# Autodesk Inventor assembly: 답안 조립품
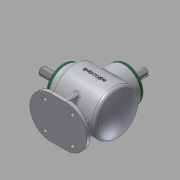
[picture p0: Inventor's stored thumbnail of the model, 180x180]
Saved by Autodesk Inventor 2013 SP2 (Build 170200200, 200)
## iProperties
Created: 2023-01
Part Number: 답안 조립품
Document SubType Name: Assembly
Designer: aa
Author: aa
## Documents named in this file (14)
- C:\Users\aa\Desktop\730106V1028\730106V1028\답안 조립품.iam
- C:\Users\aa\Desktop\730106V1025\본체.ipt
- C:\Users\aa\Desktop\730106V1025\서브 베벨기어.ipt
- C:\Users\aa\Desktop\730106V1025\오일실 17 32 8.ipt
- C:\Users\aa\Desktop\730106V1025\커버.ipt
- C:\Users\aa\Desktop\730106V1025\메인 베벨기어.ipt
- C:\Users\aa\Desktop\730106V1025\베어링 6203.ipt
- C:\Users\aa\Desktop\730106V1025\M4.ipt
- C:\Users\aa\Desktop\730106V1025\서브 축.ipt
- 서브 축.ipt
- C:\Users\aa\Desktop\730106V1025\메인 축.ipt
- 메인 축.ipt
- C:\Users\aa\Desktop\730106V1025\키 4x4.ipt
- C:\Users\aa\Desktop\730106V1025\키 5x5.ipt
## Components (5 placed, 1 different names)
1. M4:2
2. M4:1
3. M4:3
4. M4:4
5. M4:5
